Omron CX-Programmer project NewProject (CX-Programmer 9.41)

# PLC NewPLC1: CJ2M CPU12

## Program NewProgram1 (cyclic task 0)
Local symbols
BufferSize 5508 WORD
CommPortEnabledFlag_P7 A202.07 BOOL
Input_DestinationNodeNo 5021 UINT
Input_Start 5000.00 BOOL
Local_ControlWord1 5010 UINT
Local_ControlWord2 5011 UINT
Local_DestinationDeviceError 5000.06 BOOL
Local_FirstReceiveWord 5500 UINT
Local_FirstSendWord 5020 UINT
Local_PMCRError 5000.07 BOOL
Local_PMCRErrorEnd 5000.05 BOOL
Local_PMCRExecuting 5000.01 BOOL
Local_PMCRNormalEnd 5000.04 BOOL
Local_PMCR_ErrorCode 5012 UINT
Local_ResponseCode 5501 UINT[100]
Model1_2 5503 WORD
Model3_4 5504 WORD
Model5_6 5505 WORD
Model7_8 5506 WORD
Model9_10 5507 WORD
Output_DestinationDeviceErrorCode H402 UINT[2]
Output_ErrorEnd 5000.03 BOOL
Output_NormalEnd 5000.02 BOOL
Output_PMCR_ErrorCode H400 UINT
ProtocolMacroErrorCode_SCU_0_P2 1519 UINT
ProtocolMacroExecuting_SCU_0_P2 1519.15 BOOL
SequenceAbortEndCompletion_SCU_0_P2 1519.10 BOOL
SequenceEndCompletion_SCU_0_P2 1519.11 BOOL
TransmissionError_SCU_0_P2 1518.15 BOOL

### Section Section1

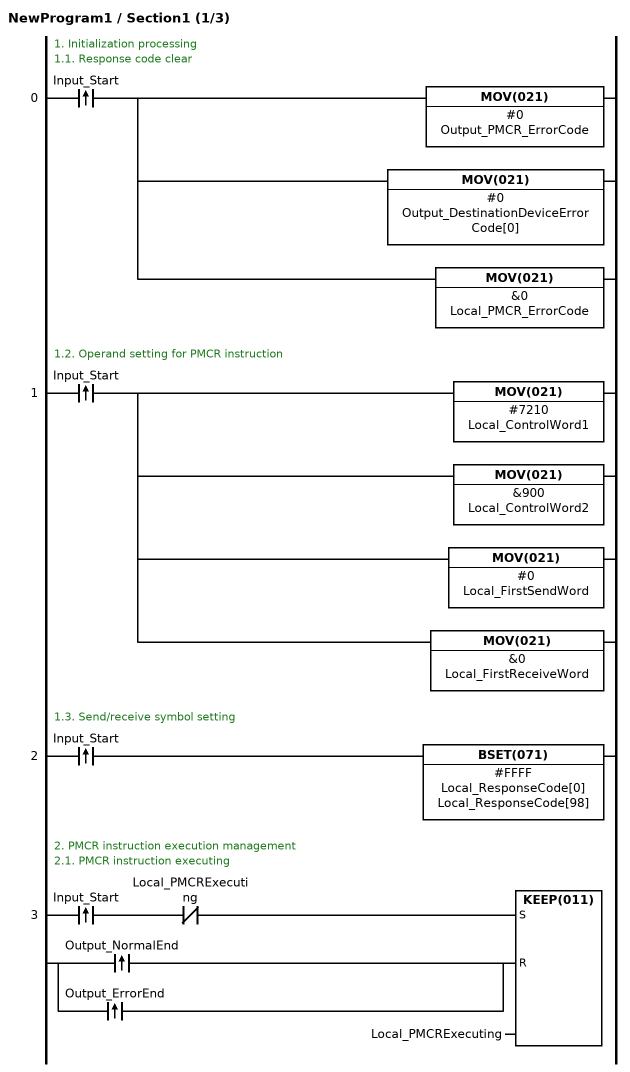
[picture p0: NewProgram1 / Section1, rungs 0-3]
; rung 0: 1. Initialization processing / 1.1. Response code clear
@LD Input_Start
MOV(021) #0 Output_PMCR_ErrorCode
MOV(021) #0 Output_DestinationDeviceErrorCode[0]
MOV(021) &0 Local_PMCR_ErrorCode
; rung 1: 1.2. Operand setting for PMCR instruction
@LD Input_Start
MOV(021) #7210 Local_ControlWord1
MOV(021) &900 Local_ControlWord2
MOV(021) #0 Local_FirstSendWord
MOV(021) &0 Local_FirstReceiveWord
; rung 2: 1.3. Send/receive symbol setting
@LD Input_Start
BSET(071) #FFFF Local_ResponseCode[0] Local_ResponseCode[98]
; rung 3: 2. PMCR instruction execution management / 2.1. PMCR instruction executing
@LD Input_Start
ANDNOT Local_PMCRExecuting
@LD Output_NormalEnd
@OR Output_ErrorEnd
KEEP(011) Local_PMCRExecuting

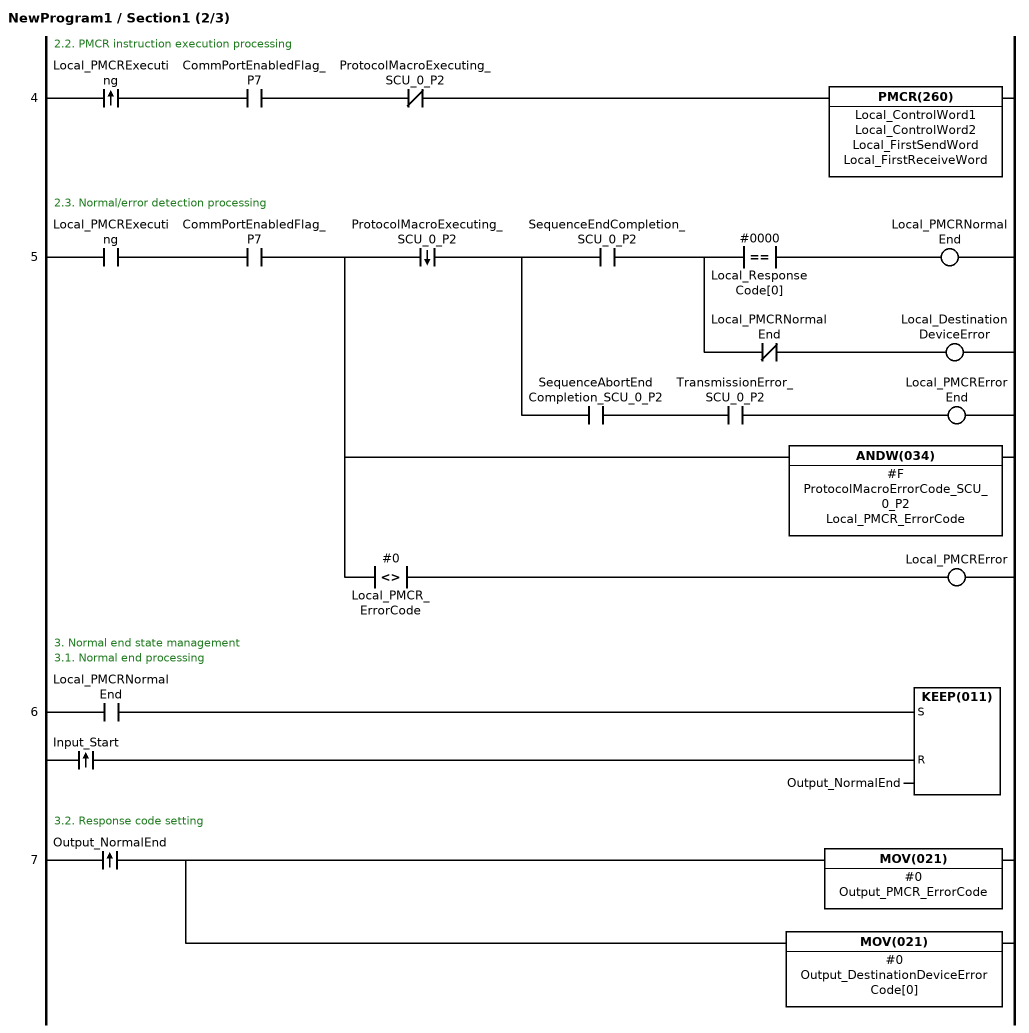
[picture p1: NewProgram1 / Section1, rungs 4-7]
; rung 4: 2.2. PMCR instruction execution processing
@LD Local_PMCRExecuting
AND CommPortEnabledFlag_P7
ANDNOT ProtocolMacroExecuting_SCU_0_P2
PMCR(260) Local_ControlWord1 Local_ControlWord2 Local_FirstSendWord Local_FirstReceiveWord
; rung 5: 2.3. Normal/error detection processing
LD Local_PMCRExecuting
AND CommPortEnabledFlag_P7
OUT TR0
%AND ProtocolMacroExecuting_SCU_0_P2
OUT TR1
AND SequenceEndCompletion_SCU_0_P2
OUT TR2
AND=(300) #0000 Local_ResponseCode[0]
OUT Local_PMCRNormalEnd
LD TR2
ANDNOT Local_PMCRNormalEnd
OUT Local_DestinationDeviceError
LD TR1
AND SequenceAbortEndCompletion_SCU_0_P2
AND TransmissionError_SCU_0_P2
OUT Local_PMCRErrorEnd
LD TR0
ANDW(034) #F ProtocolMacroErrorCode_SCU_0_P2 Local_PMCR_ErrorCode
AND<>(305) #0 Local_PMCR_ErrorCode
OUT Local_PMCRError
; rung 6: 3. Normal end state management / 3.1. Normal end processing
LD Local_PMCRNormalEnd
@LD Input_Start
KEEP(011) Output_NormalEnd
; rung 7: 3.2. Response code setting
@LD Output_NormalEnd
MOV(021) #0 Output_PMCR_ErrorCode
MOV(021) #0 Output_DestinationDeviceErrorCode[0]

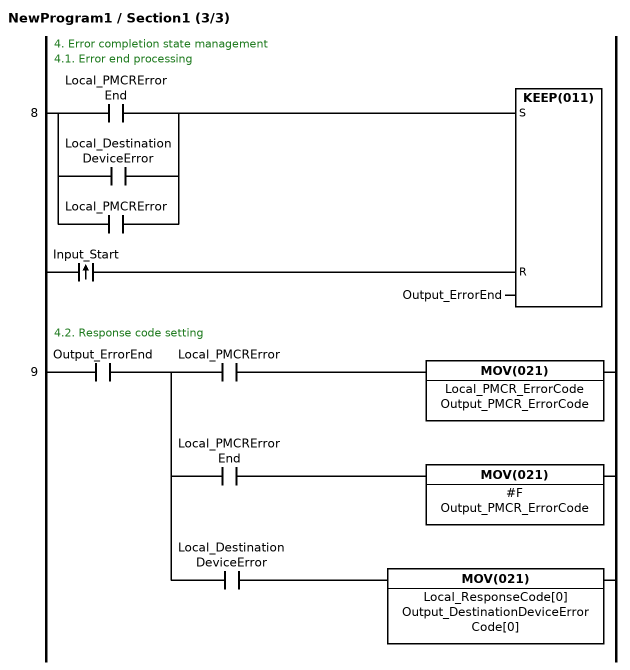
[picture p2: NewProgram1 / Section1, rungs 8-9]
; rung 8: 4. Error completion state management / 4.1. Error end processing
LD Local_PMCRErrorEnd
OR Local_DestinationDeviceError
OR Local_PMCRError
@LD Input_Start
KEEP(011) Output_ErrorEnd
; rung 9: 4.2. Response code setting
LD Output_ErrorEnd
OUT TR0
AND Local_PMCRError
MOV(021) Local_PMCR_ErrorCode Output_PMCR_ErrorCode
LD TR0
AND Local_PMCRErrorEnd
MOV(021) #F Output_PMCR_ErrorCode
LD TR0
AND Local_DestinationDeviceError
MOV(021) Local_ResponseCode[0] Output_DestinationDeviceErrorCode[0]

### Section END
; rung 0
END(001)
